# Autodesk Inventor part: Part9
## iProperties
Created: 2002-04
Part Number: Part9
Document SubType Name: Sheet Metal
Control State: 0
Master: False
Checked Out: False
Shininess: 50.0
Angle Display Precision: 2
Document Length Units: 11269
Document Angle Units: 11279
Document Time Units: 11290
Document Mass Units: 11283
Document Length Units Precision: 3
Document Angle Units Precision: 2
Density: 0.0
Volumn: 0.0
Area: 0.0
PropertySet Name: Model Information
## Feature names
1. Corner1
2. Corner2
3. Corner3
4. Corner4
5. Plate1
6. Plate7
7. Bend6
8. Plate8
9. Bend7
10. Plate9
11. Bend8
12. Plate10
13. Bend9
14. FlatPatternExtrusion1
15. Cut1
